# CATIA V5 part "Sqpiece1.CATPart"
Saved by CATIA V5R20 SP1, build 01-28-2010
Part number: Sqpiece1
Publications: "LongueurDC", "Longueur1", "Droite.4", "Droite.2", "Droite.3", "Plan.3", "Plan.2", "Plan.1", "Droite.1"
Bounding box of the stored display mesh (mm): x 0 to 280, y -20 to 20, z 0 to 0
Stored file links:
  C:\Users\RENARD Simon\Documents\Cours IFMA\2ème année\IAO\Sqpiece1.CATPart
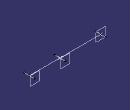
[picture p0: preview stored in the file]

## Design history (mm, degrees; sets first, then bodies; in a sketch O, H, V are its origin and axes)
Parameters
  Longueur1 = 280 mm
  LongueurDC = 160 mm
Body1 (main body)
  Point1: (0, 0, 0)
  Line1: type Normal, RefPoint Point1, RefSkin yz-plane, Start 0, End 280 {= Longueur1}
  Line2: type PtDir, RefPoint vertex of Line1, Direction zx-plane, Start -20, End 20
  Line3: type PtDir, RefPoint Point1, Direction zx-plane, Start -20, End 20
  Point2: type OnCurve, Support Line1, Length 160 {= LongueurDC}
  Line4: type PtDir, RefPoint Point2, Direction zx-plane, Start -20, End 20
  Plane1: type OffsetPt, RefPlane zx-plane, RefPoint vertex of Line3
  Plane2: type OffsetPt, RefPlane zx-plane, RefPoint vertex of Line4
  Plane3: type OffsetPt, RefPlane zx-plane, RefPoint vertex of Line2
